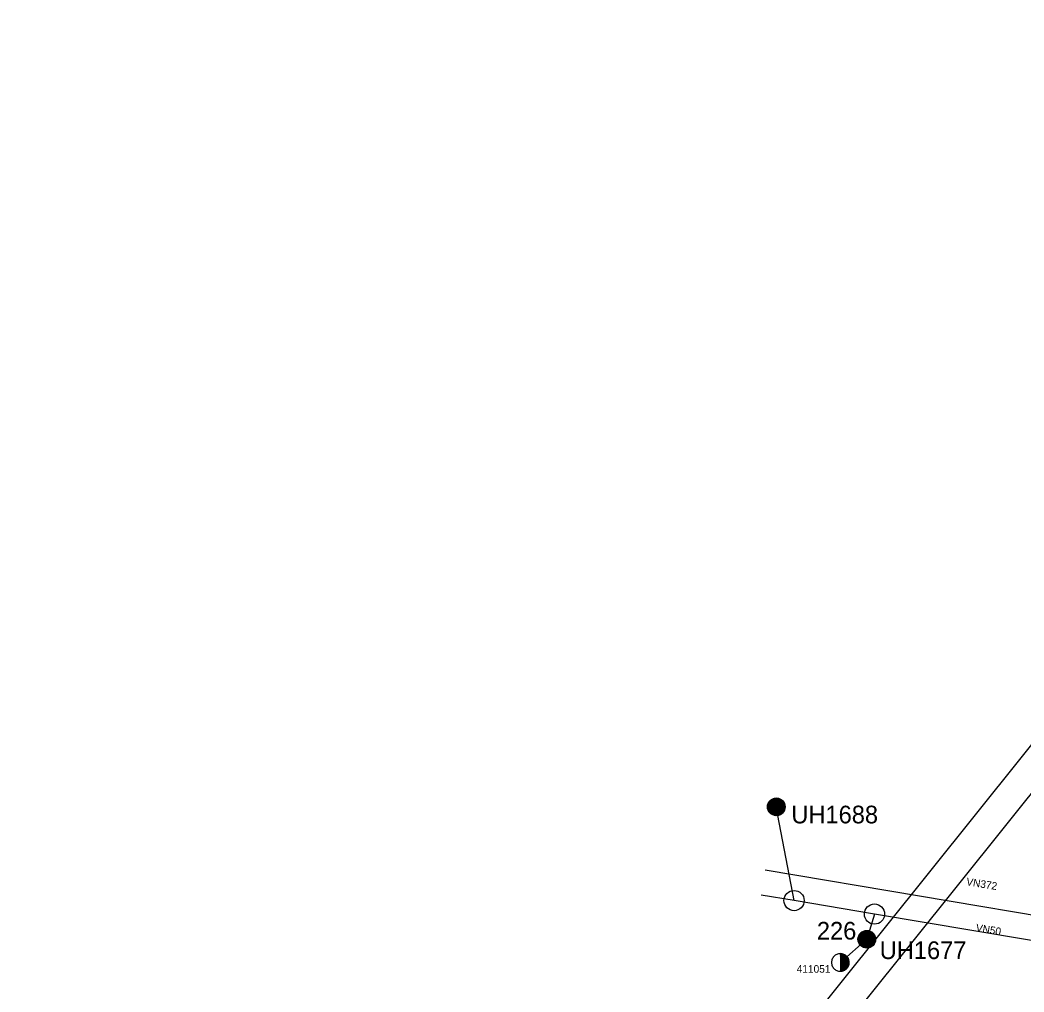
# Model space of a CAD drawing. Extents: x -541654 to -535721, y -1185255 to -1179094.
# Drawn here: x -541654 to -539667, y -1181018 to -1179094 of the extents above; entities that cross this region are included whole.
import ezdxf

# ---------------------------------------------------------------- set-up
doc = ezdxf.new("R2010")
doc.units = 0
for name, color, linetype in [('Default', 7, 'Continuous'), ('Vrstva 1', 7, 'Continuous'), ('Vrstva 2', 7, 'Continuous'), ('Vrstva 3', 7, 'Continuous'), ('Vrstva 5', 7, 'Continuous')]:
    doc.layers.add(name, color=color, linetype=linetype)

# ---------------------------------------------------------------- blocks, each defined once
blk = doc.blocks.new('PS140')
at = {"layer": 'Default'}
for p, q in [((-17.5, 0), (0, 17.5)), ((-17.4, -1.4), (1.4, 17.4)), ((-17.4, 1.5), (-1.5, 17.4)), ((-17.3, -2.6), (2.6, 17.3)), ((-17.2, 3.1), (-3.1, 17.2)), ((-17.1, -3.8), (3.8, 17.1)), ((-16.8, -4.9), (4.9, 16.8)), ((-16.8, 5), (-5, 16.8)), ((-16.4, -6), (6, 16.4)), ((-16, -7), (7, 16)), ((-15.9, 7.2), (-7.2, 15.9)), ((-15.6, -8), (8, 15.6)), ((-15.1, -8.9), (8.9, 15.1)), ((-14.5, -9.8), (9.8, 14.5)), ((-13.9, -10.6), (10.6, 13.9)), ((-13.8, 10.8), (-10.8, 13.8)), ((-13.3, -11.4), (11.4, 13.3)), ((-12.6, -12.1), (12.1, 12.6)), ((-11.9, -12.8), (12.8, 11.9)), ((-11.2, -13.5), (13.5, 11.2)), ((-10.4, -14.1), (14.1, 10.4)), ((-9.5, -14.7), (14.7, 9.5)), ((-8.6, -15.2), (15.2, 8.6)), ((-7.7, -15.7), (15.7, 7.7)), ((-6.7, -16.1), (16.1, 6.7)), ((-5.7, -16.5), (16.5, 5.7)), ((-4.6, -16.9), (16.9, 4.6)), ((-3.5, -17.1), (17.1, 3.5)), ((-2.3, -17.3), (17.3, 2.3)), ((-1, -17.5), (17.5, 1)), ((0.4, -17.5), (17.5, -0.4)), ((1.9, -17.4), (17.4, -1.9)), ((3.6, -17.1), (17.1, -3.6)), ((5.5, -16.6), (16.6, -5.5)), ((8, -15.6), (15.6, -8))]:
    blk.add_line(p, q, dxfattribs=at)
blk.add_circle((0, 0), 17.5, dxfattribs=at)
blk = doc.blocks.new('PS800')
at = {"layer": 'Vrstva 2'}
blk.add_circle((0, 0), 20, dxfattribs=at)
blk = doc.blocks.new('PS611')
at = {"layer": 'Default'}
for p, q in [((0, 16.2), (1.3, 17.4)), ((0, 14.7), (2.5, 17.3)), ((0, 13.3), (3.7, 17.1)), ((0, 11.9), (4.9, 16.8)), ((0, 10.5), (5.9, 16.4)), ((0, 9.1), (7, 16)), ((0, 7.7), (7.9, 15.6)), ((0, 6.3), (8.8, 15.1)), ((0, 4.8), (9.7, 14.5)), ((0, 3.4), (10.5, 14)), ((0, 2), (11.3, 13.3)), ((0, 0.6), (12, 12.7)), ((0, -0.8), (12.8, 12)), ((0, -2.2), (13.4, 11.2)), ((0, -3.6), (14, 10.4)), ((0, -5), (14.6, 9.6)), ((0, -6.5), (15.2, 8.7)), ((0, -7.9), (15.6, 7.8)), ((0, -9.3), (16.1, 6.8)), ((0, -10.7), (16.5, 5.8)), ((0, -12.1), (16.8, 4.7)), ((0, -13.5), (17.1, 3.6)), ((0, -14.9), (17.3, 2.4)), ((0, -16.4), (17.4, 1.1)), ((0.3, -17.5), (17.5, -0.3)), ((1.8, -17.4), (17.4, -1.8)), ((3.5, -17.1), (17.1, -3.5)), ((5.4, -16.7), (16.7, -5.4)), ((7.8, -15.7), (15.6, -7.8))]:
    blk.add_line(p, q, dxfattribs=at)
for points in [[(17.5, 0), (17.4, 1.8), (17.1, 3.6), (16.6, 5.4), (16, 7.1), (15.2, 8.8), (14.2, 10.3), (13, 11.7), (11.7, 13), (10.3, 14.2), (8.7, 15.2), (7.1, 16), (5.4, 16.6), (3.6, 17.1), (1.8, 17.4), (0, 17.5), (-1.8, 17.4), (-3.6, 17.1), (-5.4, 16.6), (-7.1, 16), (-8.8, 15.2), (-10.3, 14.2), (-11.7, 13), (-13, 11.7), (-14.2, 10.3), (-15.2, 8.7), (-16, 7.1), (-16.6, 5.4), (-17.1, 3.6), (-17.4, 1.8), (-17.5, 0), (-17.4, -1.8), (-17.1, -3.6), (-16.6, -5.4), (-16, -7.1), (-15.2, -8.8), (-14.2, -10.3), (-13, -11.7), (-11.7, -13), (-10.3, -14.2), (-8.8, -15.2), (-7.1, -16), (-5.4, -16.6), (-3.6, -17.1), (-1.8, -17.4), (0, -17.5), (1.8, -17.4), (3.6, -17.1), (5.4, -16.6), (7.1, -16), (8.8, -15.2), (10.3, -14.2), (11.7, -13), (13, -11.7), (14.2, -10.3), (15.2, -8.8), (16, -7.1), (16.6, -5.4), (17.1, -3.6), (17.4, -1.8), (17.5, 0)], [(0, 17.5), (0, -17.5)]]:
    blk.add_lwpolyline(points, dxfattribs=at)

msp = doc.modelspace()

# ---------------------------------------------------------------- linework, layer by layer
at = {"layer": 'Default'}
for points in [[(-535721.4, -1181322.7), (-538502.4, -1179093.8), (-541654.5, -1183026.4), (-538873.5, -1185255.4)], [(-535805.8, -1181332), (-538493.1, -1179178.1), (-541570.1, -1183017.1), (-538882.8, -1185171.1)]]:
    msp.add_lwpolyline(points, close=True, dxfattribs=at)
at = {"layer": 'Vrstva 1'}
for points in [[(-540157.1, -1180651.1), (-540157.9, -1180649)], [(-540121.9, -1180836.7), (-540157.1, -1180651.1)], [(-539373.7, -1180828.1), (-539567.7, -1180879.2), (-540179.2, -1180776.6)], [(-540121.9, -1180836.7), (-540187, -1180826)], [(-539962.7, -1180863.4), (-540121.9, -1180836.7)], [(-539962.7, -1180863.4), (-539977.8, -1180913.3)], [(-539458.8, -1180902.3), (-539565.4, -1180930.3), (-539962.7, -1180863.4)], [(-539977.8, -1180913.3), (-540028.6, -1180958)]]:
    msp.add_lwpolyline(points, dxfattribs=at)

# ---------------------------------------------------------------- block references
at = {"layer": 'Vrstva 2'}
for p, rotation in [((-540157.1, -1180651.1), -67.21990281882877), ((-539977.8, -1180913.3), 49.862466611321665)]:
    msp.add_blockref('PS140', p, dxfattribs=dict(at, rotation=rotation))
at = {"layer": 'Vrstva 3', "rotation": 0.17747223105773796}
msp.add_blockref('PS611', (-540030.2, -1180959.2), dxfattribs=at)
at = {"layer": 'Vrstva 5'}
for p, rotation in [((-540121.9, -1180836.7), -9.969944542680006), ((-539962.7, -1180863.4), -8.19887508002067)]:
    msp.add_blockref('PS800', p, dxfattribs=dict(at, rotation=rotation))

# ---------------------------------------------------------------- texts
at = {"layer": 'Vrstva 1'}
for s, rotation, p in [('VN372', 350.885, (-539781.6, -1180806.2)), ('VN50', 350.435, (-539762.8, -1180897.4))]:
    msp.add_text(s, height=15, rotation=rotation, dxfattribs=at).set_placement(p)
at = {"layer": 'Vrstva 2'}
for s, p in [('UH1688', (-540127.3, -1180683.9)), ('UH1677', (-539952.3, -1180952.5))]:
    msp.add_text(s, height=35, dxfattribs=at).set_placement(p)
at = {"layer": 'Vrstva 3'}
msp.add_text('411051', height=15, dxfattribs=at).set_placement((-540116.7, -1180979.5))
at = {"layer": 'Vrstva 5'}
msp.add_text('226', height=35, dxfattribs=at).set_placement((-540076.7, -1180913.9))

doc.saveas('drawing.dxf')
